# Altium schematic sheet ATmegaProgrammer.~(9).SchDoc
size A4
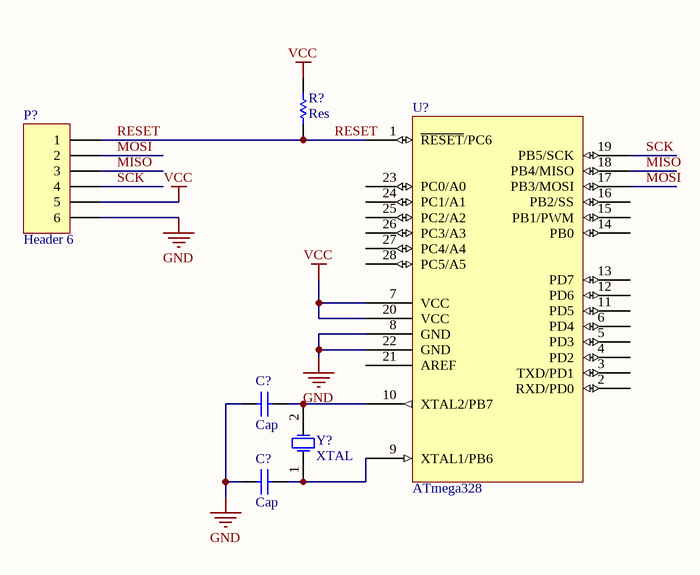
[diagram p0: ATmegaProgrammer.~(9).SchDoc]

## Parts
(Parts that share a designator on the sheet are numbered #1, #2 ... from top to bottom, then left to right.)
C?#1  Cap  [C200]
C?#2  Cap  [C200]
P?  Header 6  [HDR1X6]
R?  Res  [AXIAL-0.3]
U?  ATmega328  [DIP28]
Y?  XTAL  [XTAL4-8]

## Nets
GND: C?#1.1 C?#2.1 P?.6 U?.8(GND) U?.22(GND)
VCC: P?.5 R?.2 U?.7(VCC) U?.20(VCC)
MISO: P?.3 U?.18(PB4/MISO)
MOSI: P?.2 U?.17(PB3/MOSI)
RESET: P?.1 R?.1 U?.1(~{RESET}/PC6)
SCK: P?.4 U?.19(PB5/SCK)
NetC?#1_2: C?#1.2 U?.10(XTAL2/PB7) Y?.2(OSC2)
NetC?#2_2: C?#2.2 U?.9(XTAL1/PB6) Y?.1(OSC1)

Not connected (* = marked no-connect by the designer): U? 2(RXD/PD0) 3(TXD/PD1) 4(PD2) 5(PD3) 6(PD4) 11(PD5) 12(PD6) 13(PD7) 14(PB0) 15(PB1/PWM) 16(PB2/SS) 21(AREF) 23(PC0/A0) 24(PC1/A1) 25(PC2/A2) 26(PC3/A3) 27(PC4/A4) 28(PC5/A5)

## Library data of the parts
C?#1 C?#2 = Cap: Capacitor
P? = Header 6: Header, 6-Pin
R? = Res: Resistor
U? = ATmega328: ATmega¨t¦C³æ´¹¤ù
Y? = XTAL: Crystal Oscillator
